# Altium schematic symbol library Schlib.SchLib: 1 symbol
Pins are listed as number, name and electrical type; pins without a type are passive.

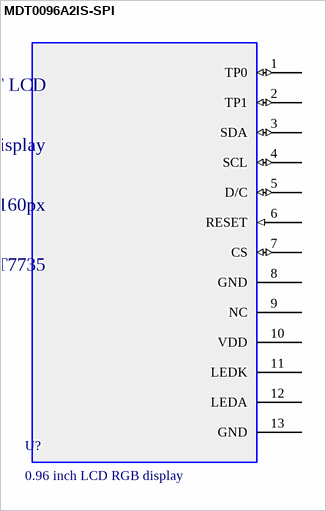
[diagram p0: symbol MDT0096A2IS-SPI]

## MDT0096A2IS-SPI
designator U?, comment 0.96 inch LCD RGB display
footprint MDT0096A2IS-SPI
pins: 1 TP0 (io), 2 TP1 (io), 3 SDA (io), 4 SCL (io), 5 D/C (io), 6 RESET (in), 7 CS (io), 8 GND (power), 9 NC, 10 VDD (power), 11 LEDK (power), 12 LEDA (power), 13 GND (power)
